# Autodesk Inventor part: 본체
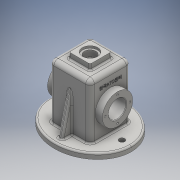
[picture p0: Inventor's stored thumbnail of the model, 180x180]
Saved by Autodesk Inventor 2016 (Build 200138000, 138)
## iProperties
Created: 2017-07
Part Number: 본체
Material: 일반
Document SubType Name: Modeling
Designer: USER
Density: 1 g/cm^3
Appearance: 기본값
Author: USER
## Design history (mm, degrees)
sketch "스케치1" dims "d14" = 75, "d15" = 65
  geometry: L1 (0, -65)-(0, 134.896); L2 (-82.834, 0)-(117.062, 0); L3 (-75, 53.384)-(-75, -73.215); L4 (75, 105.175)-(75, -110.044); 2 further points; 1 other entity
  constraints: 8 end point, 4 vertical, 4 vertical alignment, 2 horizontal alignment, 1 coincident, 1 horizontal, 1 perpendicular, 2 other
  dimensions: "d13" = 150 distance between parallel lines of L4 L3
extrude "돌출1" new body sketch "스케치1" distance "d16" = 10; taper "d17" = 0 deg
sketch "스케치2"
  geometry: L1 (-37, 110)-(37, 110); L2 (37, 110)-(37, 10); L3 (37, 10)-(-37, 10); L4 (-37, 10)-(-37, 110); L5 (65, 10)-(-65, 10) reference; L6 (-65, 0)-(65, 0) reference; 2 further points
  constraints: 8 end point, 2 parallel, 1 horizontal, 1 horizontal alignment, 1 midpoint, 1 perpendicular, 1 vertical alignment
  dimensions: "d18" = 74 distance between parallel lines of L2 L4; "d19" = 110 distance between parallel lines of L1 L6
extrude "돌출2" join sketch "스케치2" stored distance "d20" = 74; taper "d21" = 0 deg
sketch "스케치3"
  geometry: L1 (-37, 110)-(37, 110) reference; L2 (37, 110)-(37, 10) reference; L3 (-37, 10)-(37, 10) reference; L4 (-37, 10)-(-37, 110) reference; L5 (32, 105)-(-32, 105); L6 (-32, 105)-(-32, 15); L7 (-32, 15)-(32, 15); L8 (32, 15)-(32, 105); 1 further point
  constraints: 8 end point, 3 other
  dimensions: "d22" = 5 distance between parallel lines of L1 L5
extrude "돌출3" cut sketch "스케치3" stored distance "d23" = 64; taper "d24" = 0 deg
sketch "스케치4"
  geometry: L1 (-32, -32)-(32, -32); L2 (32, -32)-(32, 32); L3 (32, 32)-(-32, 32); L4 (-32, 32)-(-32, -32); 3 further points
  constraints: 8 end point, 2 midpoint, 2 parallel, 1 horizontal, 1 horizontal alignment, 1 perpendicular, 1 vertical alignment
  dimensions: "d25" = 64 distance of L3.end L1.start; "d26" = 64 distance of L2.end L3.end
extrude "돌출4" cut sketch "스케치4" stored distance "d27" = 69; taper "d28" = 0 deg
sketch "스케치5"
  geometry: 1 further point
sketch "스케치6"
  geometry: 1 further point
node "작업 평면1"
fillet "모깎기1" dims "d40" = 8
fillet "모깎기2" dims "d41" = 8
fillet "모깎기3" dims "d42" = 3
sketch "스케치15"
  geometry: L1 (0, 65)-(0, -65) reference; C1 r 27.5 at (55, 0); 2 further points
  constraints: 1 centre point, 1 horizontal alignment, 1 midpoint
  dimensions: "d56" = 55 diameter of C1; "d57" = 55 distance from line of L1 C1.centre
extrude "돌출7" join sketch "스케치15" distance "d58" = 13; taper "d59" = 0 deg
node "작업 평면2"
sketch "스케치16"
  geometry: C1 r 27.5 at (0, 0) reference; C2 r 16 at (0, 0); 1 further point
  constraints: 1 centre point, 1 coincident
  dimensions: "d60" = 32 diameter of C2
  node "투영된 루프3"
sketch "스케치17" dims "d63" = 45
  geometry: C1 r 27.5 at (0, 0) reference; 3 further points
  constraints: 2 horizontal alignment, 1 coincident, 2 other
hole "구멍2" sketch "스케치17" at (22.5, 0) diameter "d64" = 3.242; stored, may be unused: countersink angle "d68" = 90 deg, drill point angle "d70" = 118 deg; dims "d65" = 8, "d66" = 4, "d67" = 2, "d69" = 10
sketch "스케치18"
  geometry: L1 (65, 10)-(-65, 10) reference; L2 (-65, 0)-(65, 0) reference; L3 (65, 0)-(65, 10); L4 (55, 10)-(37, 82.194); L5 (37, 10)-(37, 102) reference; L6 (55, 10)-(37, 10); L7 (37, 82.194)-(37, 10); L8 (-37, 102)-(-37, 10) reference; L9 (-65, 10)-(-65, 0); L10 (-37, 82.194)-(-55, 10); L11 (-37, 82.194)-(-37, 10); L12 (65, 10)-(-65, 10) reference; L13 (-55, 10)-(-37, 10); 1 further point
  constraints: 16 end point, 4 point on line, 2 collinear, 2 perpendicular, 2 vertical
  dimensions: "d74" = 10 distance from line of L3 L4.start; "d75" = 14 deg angle of L4 L3; "d78" = 14 deg angle of L10 L9; "d79" = 10 distance from line of L9 L10.end
extrude "돌출9" join sketch "스케치18" stored distance "d80" = 8; taper "d81" = 0 deg
fillet "모깎기4" dims "d82" = 3
fillet "모깎기5" dims "d83" = 3
sketch "스케치19"
  geometry: L1 (86.305, 55)-(-68.103, 55); L2 (-29, 0)-(29, 0) reference; L3 (32, 102)-(32, 0) reference; L4 (32, 55)-(32, 82.5); L5 (32, 82.5)-(25, 75.5); L6 (25, 75.5)-(25, 55); 1 further point
  constraints: 8 end point, 4 point on line, 1 horizontal, 1 perpendicular
  dimensions: "d84" = 55 distance between parallel lines of L1 L2; "d85" = 7 distance between parallel lines of L3 L6; "d86" = 55 diameter of L4.end L1; "d87" = 135 deg angle of L3 L5
revolve "회전2" sketch "스케치19" stored, may be unused: angle "d88" = 90 deg
extrude "돌출10" cut sketch "스케치16" stored distance "d89" = 8; taper "d90" = 0 deg
sketch "스케치20"
  geometry: L1 (9, 9)-(49, 9); L2 (49, 9)-(49, 49); L3 (49, 49)-(9, 49); L4 (9, 49)-(9, 9); 3 further points
  constraints: 8 end point, 2 midpoint, 2 parallel, 1 horizontal, 1 horizontal alignment, 1 perpendicular, 1 vertical alignment
  dimensions: "d122" = 40 distance of L3.end L1.start; "d123" = 40 distance of L2.end L3.end
fillet "모깎기7" dims "d104" = 3
fillet "모깎기8" dims "d105" = 3
sketch "스케치23"
  geometry: L1 (-58, 0)-(58, 0); C1 r 5 at (-58, 0); C2 r 5 at (58, 0); 2 further points
  constraints: 2 centre point, 2 end point, 2 horizontal alignment, 1 coincident, 1 horizontal, 1 midpoint
  dimensions: "d106" = 10 diameter of C1; "d107" = 10 diameter of C2; "d109" = 58 distance of L1.start point (0, 0)
extrude "돌출14" cut sketch "스케치23" stored distance "d110" = 4; taper "d111" = 0 deg
chamfer "모따기1" distance "d112" = 1; stored, may be unused: second distance "d113" = 2, angle "d114" = 45 deg
extrude "돌출15" join sketch "스케치20" distance "d124" = 10; taper "d125" = -5 deg
sketch "스케치27"
  geometry: C1 r 14 at (29, 29); 1 further point
  constraints: 1 centre point, 1 coincident
  dimensions: "d126" = 28 diameter of C1
extrude "돌출16" cut sketch "스케치27" distance "d127" = 4; taper "d128" = 0 deg
sketch "스케치28"
  geometry: C1 r 10.5 at (0, 0); 1 further point
  constraints: 1 centre point, 1 coincident
  dimensions: "d129" = 21 diameter of C1
extrude "돌출17" cut sketch "스케치28" stored distance "d130" = 4; taper "d131" = 0 deg
fillet "모깎기10" dims "d132" = 3
fillet "모깎기11" dims "d133" = 3
sketch "스케치29"
  geometry: L1 (-120, 16.137)-(-120, -16.137) reference; L2 (-13, 37)-(-102, 37) reference; 2 further points
  constraints: 1 other
  dimensions: "d134" = 30 distance from line of point (-90, 0) L1; "d135" = 37 distance from line of L2 point (-90, 0)
feature "엠보싱2" sketch "스케치29" dims "d136" = 0.5, "d137" = 0
fillet "모깎기12" dims "d138" = 0.5
fillet "모깎기13" dims "d139" = 0.5
node "솔리드1"
mirror "대칭4"
mirror "대칭5"
mirror "대칭6"
pattern_circular "원형 패턴3" dims angle "d92" = 360 deg
mirror "대칭7"
node "투영된 루프1"
node "투영된 루프4"
